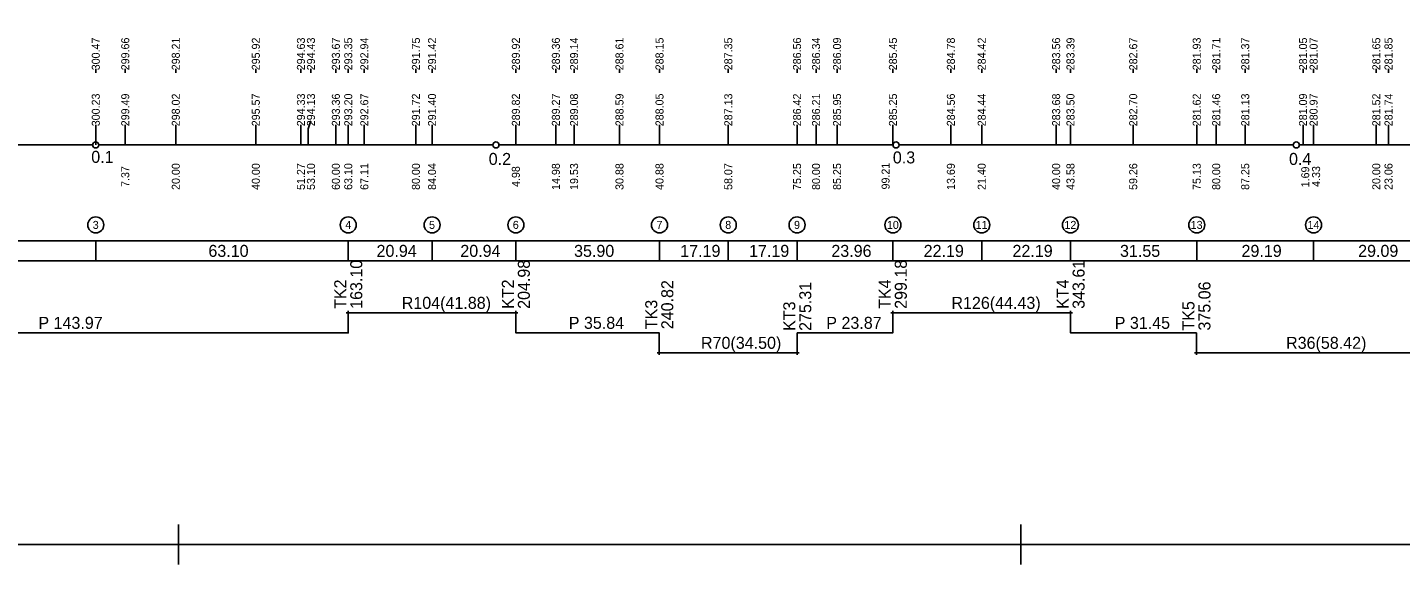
# Model space of a CAD drawing. Extents: x -24 to 1036, y -50 to 554.
# Drawn here: x 152.9 to 496.1, y -50 to 84.4 of the extents above; entities that cross this region are included whole.
import ezdxf

# ---------------------------------------------------------------- set-up
doc = ezdxf.new("R2010")
doc.units = 0
for name, color, linetype in [('SESTAVY_REZU_PO', 7, 'Continuous'), ('SMEROVE_POMERY', 7, 'Continuous'), ('SMEROVE_POMERY_KOD', 7, 'Continuous'), ('SVK', 7, 'Continuous'), ('SVK_STAT', 7, 'Continuous'), ('TABULKY', 7, 'Continuous')]:
    doc.layers.add(name, color=color, linetype=linetype)

msp = doc.modelspace()

# ---------------------------------------------------------------- linework, layer by layer
for p, q in [((190.65, -39.96), (190.65, -49.96)), ((190.65, -39.96), (190.65, -49.96)), ((190.65, -39.96), (190.65, -49.96)), ((401.15, -39.96), (401.15, -49.96)), ((401.15, -39.96), (401.15, -49.96)), ((401.15, -39.96), (401.15, -49.96)), ((401.15, -39.96), (401.15, -49.96)), ((401.15, -39.96), (401.15, -49.96)), ((401.15, -39.96), (401.15, -49.96)), ((401.15, -39.96), (401.15, -49.96)), ((401.15, -39.96), (401.15, -49.96)), ((195.65, -44.96), (185.65, -44.96)), ((195.65, -44.96), (185.65, -44.96)), ((195.65, -44.96), (185.65, -44.96)), ((195.65, -44.96), (185.65, -44.96)), ((196.15, -44.96), (186.15, -44.96)), ((196.15, -44.96), (186.15, -44.96)), ((196.15, -44.96), (186.15, -44.96)), ((196.15, -44.96), (186.15, -44.96)), ((196.15, -44.96), (186.15, -44.96)), ((196.15, -44.96), (186.15, -44.96)), ((196.15, -44.96), (186.15, -44.96)), ((196.15, -44.96), (186.15, -44.96)), ((196.15, -44.96), (186.15, -44.96)), ((196.15, -44.96), (186.15, -44.96)), ((196.15, -44.96), (186.15, -44.96)), ((196.15, -44.96), (186.15, -44.96)), ((406.15, -44.96), (396.15, -44.96)), ((406.15, -44.96), (396.15, -44.96)), ((406.15, -44.96), (396.15, -44.96)), ((406.15, -44.96), (396.15, -44.96)), ((406.15, -44.96), (396.15, -44.96)), ((406.15, -44.96), (396.15, -44.96)), ((406.15, -44.96), (396.15, -44.96)), ((406.15, -44.96), (396.15, -44.96))]:
    msp.add_line(p, q)
msp.add_lwpolyline([(1031.15, 549.04), (-19.35, 549.04), (-19.35, -44.96), (1031.15, -44.96)], close=True)
msp.add_lwpolyline([(1031.15, 549.04), (-19.35, 549.04), (-19.35, -44.96), (1031.15, -44.96)], close=True)
at = {"layer": 'SESTAVY_REZU_PO'}
for points in [[(70, 55), (169.25, 55)], [(170.75, 55), (269.25, 55)], [(270.75, 55), (369.25, 55)], [(370.75, 55), (469.25, 55)], [(470.75, 55), (569.25, 55)], [(170, 26), (170, 31)], [(233.1, 26), (233.1, 31)], [(254.04, 26), (254.04, 31)], [(274.98, 26), (274.98, 31)], [(310.88, 26), (310.88, 31)], [(328.07, 26), (328.07, 31)], [(345.25, 26), (345.25, 31)], [(369.21, 26), (369.21, 31)], [(391.4, 26), (391.4, 31)], [(413.58, 26), (413.58, 31)], [(445.13, 26), (445.13, 31)], [(474.33, 26), (474.33, 31)]]:
    msp.add_lwpolyline(points, dxfattribs=at)
for centre in [(170, 55), (270, 55), (370, 55), (470, 55)]:
    msp.add_circle(centre, 0.75, dxfattribs=at)
at = {"layer": 'SMEROVE_POMERY'}
msp.add_lwpolyline([(70, 8), (79.06, 8), (79.06, 3), (89.13, 3), (89.13, 8), (233.1, 8), (233.1, 13), (274.98, 13), (274.98, 8), (310.82, 8), (310.82, 3), (345.31, 3), (345.31, 8), (369.18, 8), (369.18, 13), (413.61, 13), (413.61, 8), (445.06, 8), (445.06, 3), (503.48, 3)], dxfattribs=at)
at = {"layer": 'SMEROVE_POMERY_KOD'}
for points in [[(232.6, 13), (233.6, 13)], [(233.1, 12.5), (233.1, 13.5)], [(274.48, 13), (275.48, 13)], [(274.98, 12.5), (274.98, 13.5)], [(368.68, 13), (369.68, 13)], [(369.18, 12.5), (369.18, 13.5)], [(413.11, 13), (414.11, 13)], [(413.61, 12.5), (413.61, 13.5)], [(310.82, 2.5), (310.82, 3.5)], [(345.31, 2.5), (345.31, 3.5)], [(445.06, 2.5), (445.06, 3.5)], [(310.32, 3), (311.32, 3)], [(344.81, 3), (345.81, 3)], [(444.56, 3), (445.56, 3)]]:
    msp.add_lwpolyline(points, dxfattribs=at)
at = {"layer": 'SVK'}
for points in [[(190, 73), (190, 74)], [(210, 73), (210, 74)], [(230, 73), (230, 74)], [(250, 73), (250, 74)], [(350, 73), (350, 74)], [(383.69, 73), (383.69, 74)], [(410, 73), (410, 74)], [(450, 73), (450, 74)], [(490, 73), (490, 74)], [(190, 55), (190, 60)], [(210, 55), (210, 60)], [(230, 55), (230, 60)], [(250, 55), (250, 60)], [(350, 55), (350, 60)], [(383.69, 55), (383.69, 60)], [(410, 55), (410, 60)], [(450, 55), (450, 60)], [(490, 55), (490, 60)]]:
    msp.add_lwpolyline(points, dxfattribs=at)
at = {"layer": 'SVK_STAT'}
for points in [[(170, 73), (170, 74)], [(177.37, 73), (177.37, 74)], [(221.27, 73), (221.27, 74)], [(223.77, 73), (223.77, 74)], [(233.1, 73), (233.1, 74)], [(237.11, 73), (237.11, 74)], [(254.04, 73), (254.04, 74)], [(274.98, 73), (274.98, 74)], [(284.98, 73), (284.98, 74)], [(289.53, 73), (289.53, 74)], [(300.88, 73), (300.88, 74)], [(310.88, 73), (310.88, 74)], [(328.07, 73), (328.07, 74)], [(345.25, 73), (345.25, 74)], [(355.25, 73), (355.25, 74)], [(369.21, 73), (369.21, 74)], [(391.4, 73), (391.4, 74)], [(413.58, 73), (413.58, 74)], [(429.26, 73), (429.26, 74)], [(445.13, 73), (445.13, 74)], [(457.25, 73), (457.25, 74)], [(471.69, 73), (471.69, 74)], [(474.33, 73), (474.33, 74)], [(493.06, 73), (493.06, 74)], [(170, 55), (170, 60)], [(177.37, 55), (177.37, 60)], [(221.27, 55), (221.27, 60)], [(223.1, 55), (223.1, 59), (223.77, 61)], [(233.1, 55), (233.1, 60)], [(237.11, 55), (237.11, 60)], [(254.04, 55), (254.04, 60)], [(274.98, 55), (274.98, 60)], [(284.98, 55), (284.98, 60)], [(289.53, 55), (289.53, 60)], [(300.88, 55), (300.88, 60)], [(310.88, 55), (310.88, 60)], [(328.07, 55), (328.07, 60)], [(345.25, 55), (345.25, 60)], [(355.25, 55), (355.25, 60)], [(369.21, 55), (369.21, 60)], [(391.4, 55), (391.4, 60)], [(413.58, 55), (413.58, 60)], [(429.26, 55), (429.26, 60)], [(445.13, 55), (445.13, 60)], [(457.25, 55), (457.25, 60)], [(471.69, 55), (471.69, 60)], [(474.33, 55), (474.33, 60)], [(493.06, 55), (493.06, 60)]]:
    msp.add_lwpolyline(points, dxfattribs=at)
for centre in [(170, 35), (233.1, 35), (254.04, 35), (274.98, 35), (310.88, 35), (328.07, 35), (345.25, 35), (369.21, 35), (391.4, 35), (413.58, 35), (445.13, 35), (474.33, 35)]:
    msp.add_circle(centre, 2, dxfattribs=at)
at = {"layer": 'TABULKY'}
msp.add_lwpolyline([(70, 26), (859.4, 26), (859.4, 31), (70, 31), (70, 26)], dxfattribs=at)

# ---------------------------------------------------------------- texts
at = {"layer": 'SESTAVY_REZU_PO'}
for s, p in [('0.1', (168.88, 50.52)), ('0.2', (268.2, 50)), ('0.3', (369.19, 50.38)), ('0.4', (468.2, 50)), ('63.10', (198.15, 27)), ('20.94', (240.17, 27)), ('20.94', (261.11, 27)), ('35.90', (289.53, 27)), ('17.19', (316.07, 27)), ('17.19', (333.26, 27)), ('23.96', (353.83, 27)), ('22.19', (376.9, 27)), ('22.19', (399.09, 27)), ('31.55', (425.96, 27)), ('29.19', (456.33, 27)), ('29.09', (485.47, 27))]:
    msp.add_text(s, height=3, dxfattribs=at).set_placement(p)
at = {"layer": 'SMEROVE_POMERY'}
for s, p in [('R104(41.88)', (246.47, 14)), ('R126(44.43)', (383.83, 14)), ('P 143.97', (155.67, 9)), ('P 35.84', (288.21, 9)), ('P 23.87', (352.56, 9)), ('P 31.45', (424.64, 9)), ('R70(34.50)', (321.25, 4)), ('R36(58.42)', (467.46, 4))]:
    msp.add_text(s, height=3, dxfattribs=at).set_placement(p)
at = {"layer": 'SMEROVE_POMERY_KOD'}
for s, p in [('163.10', (236.6, 14)), ('204.98', (278.48, 14)), ('299.18', (372.68, 14)), ('343.61', (417.11, 14)), ('TK2', (232.6, 14)), ('KT2', (274.48, 14)), ('240.82', (314.32, 8.91)), ('TK4', (368.68, 14)), ('KT4', (413.11, 14)), ('375.06', (448.56, 8.57)), ('275.31', (348.81, 8.48)), ('TK3', (310.32, 8.91)), ('KT3', (344.81, 8.48)), ('TK5', (444.56, 8.57))]:
    msp.add_text(s, height=3, rotation=90, dxfattribs=at).set_placement(p)
at = {"layer": 'SVK'}
for s, p in [(' 298.21', (191, 72.93)), (' 295.92', (211, 72.93)), (' 293.67', (231, 72.93)), (' 291.75', (251, 72.93)), (' 286.34', (351, 72.93)), (' 284.78', (384.69, 72.93)), (' 283.56', (411, 72.93)), (' 281.71', (451, 72.93)), (' 281.65', (491, 72.93)), (' 298.02', (191, 58.93)), (' 295.57', (211, 58.93)), (' 293.36', (231, 58.93)), (' 291.72', (251, 58.93)), (' 286.21', (351, 58.93)), (' 284.56', (384.69, 58.93)), (' 283.68', (411, 58.93)), (' 281.46', (451, 58.93)), (' 281.52', (491, 58.93)), (' 20.00', (191, 43)), (' 40.00', (211, 43)), (' 60.00', (231, 43)), (' 80.00', (251, 43)), (' 80.00', (351, 43)), (' 13.69', (384.69, 43)), (' 40.00', (411, 43)), (' 80.00', (451, 43)), (' 20.00', (491, 43))]:
    msp.add_text(s, height=2, rotation=90, dxfattribs=at).set_placement(p)
at = {"layer": 'SVK_STAT'}
for s, p in [(' 300.47', (171, 72.93)), (' 299.66', (178.37, 72.93)), (' 294.63', (222.27, 72.93)), (' 294.43', (224.77, 72.93)), (' 293.35', (234.1, 72.93)), (' 292.94', (238.11, 72.93)), (' 291.42', (255.04, 72.93)), (' 289.92', (275.98, 72.93)), (' 289.36', (285.98, 72.93)), (' 289.14', (290.53, 72.93)), (' 288.61', (301.88, 72.93)), (' 288.15', (311.88, 72.93)), (' 287.35', (329.07, 72.93)), (' 286.56', (346.25, 72.93)), (' 286.09', (356.25, 72.93)), (' 285.45', (370.21, 72.93)), (' 284.42', (392.4, 72.93)), (' 283.39', (414.58, 72.93)), (' 282.67', (430.26, 72.93)), (' 281.93', (446.13, 72.93)), (' 281.37', (458.25, 72.93)), (' 281.05', (472.69, 72.93)), (' 281.07', (475.33, 72.93)), (' 281.85', (494.06, 72.93)), (' 300.23', (171, 58.93)), (' 299.49', (178.37, 58.93)), (' 294.33', (222.27, 58.93)), (' 294.13', (224.77, 58.93)), (' 293.20', (234.1, 58.93)), (' 292.67', (238.11, 58.93)), (' 291.40', (255.04, 58.93)), (' 289.82', (275.98, 58.93)), (' 289.27', (285.98, 58.93)), (' 289.08', (290.53, 58.93)), (' 288.59', (301.88, 58.93)), (' 288.05', (311.88, 58.93)), (' 287.13', (329.07, 58.93)), (' 286.42', (346.25, 58.93)), (' 285.95', (356.25, 58.93)), (' 285.25', (370.21, 58.93)), (' 284.44', (392.4, 58.93)), (' 283.50', (414.58, 58.93)), (' 282.70', (430.26, 58.93)), (' 281.62', (446.13, 58.93)), (' 281.13', (458.25, 58.93)), (' 281.09', (472.69, 58.93)), (' 280.97', (475.33, 58.93)), (' 281.74', (494.06, 58.93)), ('  7.37', (178.37, 43)), (' 51.27', (222.27, 43)), (' 53.10', (224.77, 43)), (' 63.10', (234.1, 43)), (' 67.11', (238.11, 43)), (' 84.04', (255.04, 43)), ('  4.98', (275.98, 43)), (' 14.98', (285.98, 43)), (' 19.53', (290.53, 43)), (' 30.88', (301.88, 43)), (' 40.88', (311.88, 43)), (' 58.07', (329.07, 43)), (' 75.25', (346.25, 43)), (' 85.25', (356.25, 43)), (' 99.21', (368.38, 43.12)), (' 21.40', (392.4, 43)), (' 43.58', (414.58, 43)), (' 59.26', (430.26, 43)), (' 75.13', (446.13, 43)), (' 87.25', (458.25, 43)), ('  1.69', (473.25, 42.91)), ('  4.33', (475.96, 43.02)), (' 23.06', (494.06, 43))]:
    msp.add_text(s, height=2, rotation=90, dxfattribs=at).set_placement(p)
for s, p in [('3', (169.25, 34)), ('4', (232.35, 34)), ('5', (253.29, 34)), ('6', (274.22, 34)), ('7', (310.13, 34)), ('8', (327.31, 34)), ('9', (344.5, 34)), ('10', (367.7, 34)), ('11', (389.89, 34)), ('12', (412.07, 34)), ('13', (443.62, 34)), ('14', (472.82, 34))]:
    msp.add_text(s, height=2, dxfattribs=at).set_placement(p)

doc.saveas('drawing.dxf')
